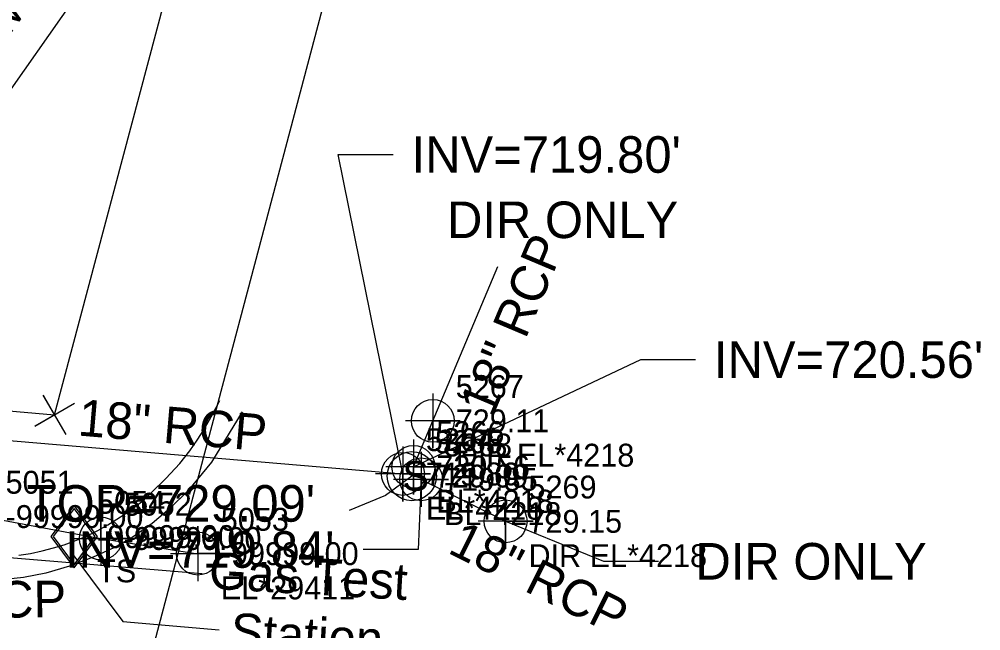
# Model space of a CAD drawing. Extents: x 1516784 to 1522736, y 634838 to 639369.
# Drawn here: x 1520954.6 to 1521059.7, y 638772.7 to 638839.5 of the extents above; entities that cross this region are included whole.
import ezdxf

# ---------------------------------------------------------------- set-up
doc = ezdxf.new("R2010")
doc.units = 0
for name, color, linetype in [('COGO Default Point Number', 7, 'Continuous'), ('Exist Environmental Wetland Boundary Cogo Number', 7, 'Continuous'), ('Exist Property Corner CELL', 7, 'Continuous'), ('Exist Property Line', 7, 'Continuous'), ('Exist Right of Way Line', 7, 'Continuous'), ('Exist Structure Minor Pipes CMP 54 Inch', 7, 'Continuous'), ('Exist Structure Minor Pipes CMP 54 Inch Text', 7, 'Continuous'), ('Exist Structure Minor Pipes RCP 18 Inch', 7, 'Continuous'), ('Exist Structure Minor Pipes RCP 18 Inch Cogo Comment', 7, 'Continuous'), ('Exist Structure Minor Pipes RCP 18 Inch Cogo Elevation', 7, 'Continuous'), ('Exist Structure Minor Pipes RCP 18 Inch Cogo Number', 7, 'Continuous'), ('Exist Structure Minor Pipes RCP 18 Inch Cogo Point CELL', 7, 'Continuous'), ('Exist Structure Minor Pipes RCP 18 Inch Invert', 7, 'Continuous'), ('Exist Structure Minor Pipes RCP 18 Inch Leader', 7, 'Continuous'), ('Exist Structure Minor Pipes RCP 18 Inch Text', 7, 'Continuous'), ('Exist Structure Minor Pipes RCP 60 Inch Text', 7, 'Continuous'), ('Exist Structure Minor Storm Sewer Manhole CELL', 7, 'Continuous'), ('Exist Structure Minor Storm Sewer Manhole Cogo Elevation', 7, 'Continuous'), ('Exist Structure Minor Storm Sewer Manhole Cogo Number', 7, 'Continuous'), ('Exist Structure Minor Storm Sewer Manhole Leader', 7, 'Continuous'), ('Exist Structure Minor Storm Sewer Manhole Text', 7, 'Continuous'), ('Exist Utilities Gas UG Line SUE LOS B', 7, 'Continuous'), ('Exist Utilities Gas UG Line SUE LOS B Cogo Comment', 7, 'Continuous'), ('Exist Utilities Gas UG Line SUE LOS B Cogo Elevation', 7, 'Continuous'), ('Exist Utilities Gas UG Line SUE LOS B Cogo Number', 7, 'Continuous'), ('Exist Utilities Gas UG Line SUE LOS B Cogo Point CELL', 7, 'Continuous'), ('Exist Utilities Gas Valve CELL', 7, 'Continuous'), ('Exist Utilities Gas Valve Cogo Comment', 7, 'Continuous'), ('Exist Utilities Gas Valve Cogo Elevation', 7, 'Continuous'), ('Exist Utilities Gas Valve Cogo Number', 7, 'Continuous'), ('Exist Utilities Gas Valve Leader', 7, 'Continuous'), ('Exist Utilities Gas Valve Text', 7, 'Continuous'), ('Exist Utilities Sanitary Sewer UG Line', 7, 'Continuous'), ('Exist Utilities Water UG Line SUE LOS C', 7, 'Continuous')]:
    doc.layers.add(name, color=color, linetype=linetype)

msp = doc.modelspace()

# ---------------------------------------------------------------- linework, layer by layer
at = {"layer": 'COGO Default Point Number'}
msp.add_lwpolyline([(1520978.98, 638796.62), (1520975.65, 638791.13), (1520973.09, 638788.02), (1520971.11, 638786.06), (1520969.16, 638784.43), (1520966.97, 638782.91), (1520964.97, 638781.78), (1520962.71, 638780.73), (1520960.13, 638779.74), (1520957.55, 638778.99), (1520955.11, 638778.51), (1520953.06, 638778.3)], dxfattribs=at)
at = {"layer": 'Exist Environmental Wetland Boundary Cogo Number'}
msp.add_lwpolyline([(1520954.59, 638780.97), (1520955.86, 638781.16), (1520957.15, 638781.43), (1520958.4, 638781.76), (1520959.55, 638782.1), (1520960.71, 638782.51), (1520961.98, 638783.04), (1520963.23, 638783.64), (1520964.33, 638784.26), (1520965.32, 638784.88), (1520966.23, 638785.48), (1520967.1, 638786.1), (1520967.99, 638786.8), (1520969.1, 638787.8), (1520970.64, 638789.33), (1520972.17, 638790.99), (1520973.27, 638792.36), (1520974.09, 638793.55), (1520974.82, 638794.67), (1520975.75, 638796.33), (1520976.54, 638797.86)], dxfattribs=at)
at = {"layer": 'Exist Property Corner CELL'}
msp.add_line((1520958.51, 638796.3), (1520958.51, 638796.3), dxfattribs=at)
msp.add_lwpolyline([(1520959.77, 638794.14), (1520957.26, 638798.46), (1520958.51, 638796.3), (1520956.35, 638795.05), (1520960.67, 638797.56)], dxfattribs=at)
at = {"layer": 'Exist Property Line'}
msp.add_line((1520958.51, 638796.3), (1521017.53, 639018.87), dxfattribs=at)
at = {"layer": 'Exist Right of Way Line'}
msp.add_line((1520625.53, 638826.37), (1520958.51, 638796.3), dxfattribs=at)
at = {"layer": 'Exist Structure Minor Pipes CMP 54 Inch'}
msp.add_line((1520990.82, 638884.93), (1520930.05, 638798.08), dxfattribs=at)
at = {"layer": 'Exist Structure Minor Pipes RCP 18 Inch'}
for p, q in [((1520997.7, 638790.61), (1521006.93, 638812.51)), ((1520931.58, 638795.37), (1520996.56, 638789.84)), ((1520997.7, 638790.61), (1520999.82, 638795.64)), ((1520998.54, 638789.25), (1521007.77, 638784.66))]:
    msp.add_line(p, q, dxfattribs=at)
at = {"layer": 'Exist Structure Minor Pipes RCP 18 Inch Cogo Point CELL'}
for points in [[(1520999.82, 638798.64), (1520999.82, 638792.64), (1520999.82, 638795.64), (1521002.82, 638795.64), (1520996.82, 638795.64)], [(1520997.7, 638793.61), (1520997.7, 638787.61), (1520997.7, 638790.61), (1521000.7, 638790.61), (1520994.7, 638790.61)], [(1520996.56, 638792.84), (1520996.56, 638786.84), (1520996.56, 638789.84), (1520999.56, 638789.84), (1520993.56, 638789.84)], [(1520998.54, 638792.25), (1520998.54, 638786.25), (1520998.54, 638789.25), (1521001.54, 638789.25), (1520995.54, 638789.25)], [(1521007.77, 638787.66), (1521007.77, 638781.66), (1521007.77, 638784.66), (1521010.77, 638784.66), (1521004.77, 638784.66)]]:
    msp.add_lwpolyline(points, dxfattribs=at)
for centre in [(1520999.82, 638795.64), (1520996.56, 638789.84), (1520997.7, 638790.61), (1520998.54, 638789.25), (1521007.77, 638784.66)]:
    msp.add_circle(centre, 2.34, dxfattribs=at)
at = {"layer": 'Exist Structure Minor Pipes RCP 18 Inch Leader'}
for points in [[(1520996.56, 638789.84), (1520989.5, 638824.76), (1520995.5, 638824.76)], [(1520997.7, 638790.61), (1521022.53, 638802.34), (1521028.53, 638802.34)], [(1520998.54, 638789.25), (1520998.21, 638781.58), (1520992.21, 638781.58)], [(1521007.77, 638784.66), (1521018.46, 638780.29), (1521024.46, 638780.29)]]:
    msp.add_lwpolyline(points, dxfattribs=at)
at = {"layer": 'Exist Structure Minor Storm Sewer Manhole CELL'}
msp.add_circle((1520997.53, 638789.6), 2.69, dxfattribs=at)
at = {"layer": 'Exist Structure Minor Storm Sewer Manhole Leader'}
msp.add_lwpolyline([(1520997.53, 638789.6), (1520994.67, 638787.49), (1520990.69, 638785.86)], dxfattribs=at)
at = {"layer": 'Exist Utilities Gas UG Line SUE LOS B'}
msp.add_lwpolyline([(1520539.18, 638834.88), (1520564.68, 638828.5), (1520580.05, 638824.16), (1520598.76, 638820.41), (1520612.09, 638817.18), (1520628.44, 638812.31), (1520643.86, 638808.13), (1520657.23, 638806.83), (1520690.69, 638805.1), (1520711.42, 638804.62), (1520742.75, 638803.38), (1520783.34, 638801.18), (1520808.89, 638798.59), (1520838.89, 638796.57), (1520867.95, 638793.41), (1520888.08, 638792.2), (1520918.9, 638789.34), (1520950.66, 638785.18), (1520963.56, 638782.78), (1520974.16, 638781.12)], dxfattribs=at)
at = {"layer": 'Exist Utilities Gas UG Line SUE LOS B Cogo Point CELL'}
for points in [[(1520960.55, 638782.78), (1520966.55, 638782.78), (1520963.55, 638782.78), (1520963.55, 638785.78), (1520963.55, 638779.78)], [(1520971.16, 638781.13), (1520977.16, 638781.13), (1520974.16, 638781.13), (1520974.16, 638784.13), (1520974.16, 638778.13)]]:
    msp.add_lwpolyline(points, dxfattribs=at)
for centre in [(1520963.55, 638782.78), (1520974.16, 638781.13)]:
    msp.add_circle(centre, 2.34, dxfattribs=at)
at = {"layer": 'Exist Utilities Gas Valve CELL'}
msp.add_line((1520960.65, 638782.99), (1520960.65, 638782.99), dxfattribs=at)
msp.add_lwpolyline([(1520960.65, 638786.4), (1520958.11, 638782.99), (1520960.65, 638779.58), (1520963.18, 638782.99), (1520960.65, 638786.4)], dxfattribs=at)
msp.add_lwpolyline([(1520962.94, 638782.99), (1520960.65, 638786.07), (1520958.36, 638782.99), (1520960.65, 638779.91)], close=True, dxfattribs=at)
at = {"layer": 'Exist Utilities Gas Valve Leader'}
msp.add_lwpolyline([(1520960.6, 638780.88), (1520965.95, 638773.72), (1520976.5, 638772.79)], dxfattribs=at)
at = {"layer": 'Exist Utilities Sanitary Sewer UG Line'}
msp.add_line((1520965.57, 638756.83), (1521015.43, 638945.09), dxfattribs=at)
at = {"layer": 'Exist Utilities Water UG Line SUE LOS C'}
msp.add_line((1520674.92, 638803.91), (1520974.62, 638778.94), dxfattribs=at)

# ---------------------------------------------------------------- texts
at = {"layer": 'Exist Structure Minor Pipes CMP 54 Inch Text'}
msp.add_text('54" CMP', height=4, rotation=55.019, dxfattribs=at).set_placement((1520945.92, 638826.78))
at = {"layer": 'Exist Structure Minor Pipes RCP 18 Inch Cogo Comment'}
for s, p in [('DIR EL*4218', (1521002.32, 638790.64)), ('BL*4218', (1521000.2, 638785.61)), ('EL*4218', (1520999.06, 638784.84)), ('BL*4218', (1521001.04, 638784.25)), ('DIR EL*4218', (1521010.27, 638779.66))]:
    msp.add_text(s, height=2.5, dxfattribs=at).set_placement(p)
at = {"layer": 'Exist Structure Minor Pipes RCP 18 Inch Cogo Elevation'}
for s, p in [('729.11', (1521002.32, 638794.39)), ('719.80', (1520999.06, 638788.59)), ('720.56', (1521000.2, 638789.36)), ('719.85', (1521001.04, 638788)), ('729.15', (1521010.27, 638783.41))]:
    msp.add_text(s, height=2.5, dxfattribs=at).set_placement(p)
at = {"layer": 'Exist Structure Minor Pipes RCP 18 Inch Cogo Number'}
for s, p in [('5267', (1521002.32, 638798.14)), ('5266', (1521000.2, 638793.11)), ('5264', (1520999.06, 638792.34)), ('5268', (1521001.04, 638791.75)), ('5269', (1521010.27, 638787.16))]:
    msp.add_text(s, height=2.5, dxfattribs=at).set_placement(p)
at = {"layer": 'Exist Structure Minor Pipes RCP 18 Inch Invert'}
for s, p in [("INV=719.80'", (1520997.5, 638822.76)), ('DIR ONLY', (1521001.37, 638815.62)), ("INV=720.56'", (1521030.53, 638800.34)), ("INV=719.84'", (1520959.66, 638779.58)), ('DIR ONLY', (1521028.51, 638778.29))]:
    msp.add_text(s, height=4, dxfattribs=at).set_placement(p)
at = {"layer": 'Exist Structure Minor Pipes RCP 18 Inch Text'}
for rotation, p in [(67.1378, (1521006.31, 638795.89)), (355.1429, (1520960.97, 638794.05)), (333.5494, (1521001.32, 638781.27))]:
    msp.add_text('18" RCP', height=4, rotation=rotation, dxfattribs=at).set_placement(p)
at = {"layer": 'Exist Structure Minor Pipes RCP 60 Inch Text'}
msp.add_text('60" RCP', height=4, rotation=0.5289, dxfattribs=at).set_placement((1520939.16, 638774))
at = {"layer": 'Exist Structure Minor Storm Sewer Manhole CELL'}
msp.add_text('S', height=3.25, dxfattribs=at).set_placement((1520996.5, 638788))
at = {"layer": 'Exist Structure Minor Storm Sewer Manhole Cogo Elevation'}
msp.add_text('729.09', height=2.5, dxfattribs=at).set_placement((1521000.03, 638788.35))
at = {"layer": 'Exist Structure Minor Storm Sewer Manhole Cogo Number'}
msp.add_text('5265', height=2.5, dxfattribs=at).set_placement((1521000.03, 638792.1))
at = {"layer": 'Exist Structure Minor Storm Sewer Manhole Text'}
msp.add_text("TOP=729.09'", height=4, dxfattribs=at).set_placement((1520955.46, 638784.62))
at = {"layer": 'Exist Utilities Gas UG Line SUE LOS B Cogo Comment'}
msp.add_text('EL*29411', height=2.5, dxfattribs=at).set_placement((1520976.66, 638776.13))
at = {"layer": 'Exist Utilities Gas UG Line SUE LOS B Cogo Elevation'}
for p in [(1520953.15, 638783.93), (1520966.05, 638781.53), (1520976.66, 638779.88)]:
    msp.add_text('-99999.00', height=2.5, dxfattribs=at).set_placement(p)
at = {"layer": 'Exist Utilities Gas UG Line SUE LOS B Cogo Number'}
for s, p in [('5051', (1520953.15, 638787.68)), ('5052', (1520966.05, 638785.28)), ('5053', (1520976.66, 638783.63))]:
    msp.add_text(s, height=2.5, dxfattribs=at).set_placement(p)
at = {"layer": 'Exist Utilities Gas Valve Cogo Comment'}
msp.add_text('TS', height=2.5, dxfattribs=at).set_placement((1520963.15, 638777.99))
at = {"layer": 'Exist Utilities Gas Valve Cogo Elevation'}
msp.add_text('-99999.00', height=2.5, dxfattribs=at).set_placement((1520963.15, 638781.74))
at = {"layer": 'Exist Utilities Gas Valve Cogo Number'}
msp.add_text('5054', height=2.5, dxfattribs=at).set_placement((1520963.15, 638785.49))
at = {"layer": 'Exist Utilities Gas Valve Text'}
for s, p in [('Gas Test', (1520975.28, 638777.31)), ('Station', (1520977.64, 638770.67))]:
    msp.add_text(s, height=4, rotation=356.6804, dxfattribs=at).set_placement(p)

doc.saveas('drawing.dxf')
